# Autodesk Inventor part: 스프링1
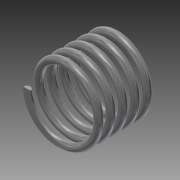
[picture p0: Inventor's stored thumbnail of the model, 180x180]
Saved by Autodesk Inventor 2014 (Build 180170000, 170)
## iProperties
Created: 2016-10
Part Number: 스프링1
Material: 강철, 탄소
Document SubType Name: Modeling
Designer: 703-16
Density: 7.87 g/cm^3
Appearance: 반연마
Mass: 6.8717 g
Surface Area: 17.7337 cm^2
Volume: 0.873151 cm^3
Author: 703-16
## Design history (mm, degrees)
sketch "스케치1"
  geometry: L1 (0, 0)-(-9, 0); L2 (-9, 0)-(-9, 16.67); L3 (-9, 16.67)-(0, 16.67); L4 (0, 16.67)-(0, 0); C1 r 1 at (-9, 0)
  constraints: 8 end point, 2 parallel, 1 centre point, 1 coincident, 1 horizontal, 1 perpendicular
  dimensions: "d0" = 16.66987 distance of L3.end L1.start (derived); "d1" = 2 diameter of C1; "d2" = 18 diameter of L2 L4
feature "코일1" sketch "스케치1" pitch "d3" = 10; turns "d5" = 5; dims "d4" = 16.66987 (= d0), "d6" = 0, angle "d7" = 90 deg, angle "d8" = 90 deg, "d9" = 0, "d10" = 0
node "작업 평면1"
sketch "스케치2"
  geometry: L1 (0, 0)-(-2, 0) reference; 1 further point
  constraints: 1 horizontal alignment
extrude "돌출1" cut sketch "스케치2" distance "d11" = 10; taper "d12" = 0 deg
sketch "스케치3"
  geometry: L1 (8, 0)-(10, 0) reference; 1 further point
  constraints: 1 horizontal alignment
extrude "돌출2" cut sketch "스케치3" distance "d13" = 10; taper "d14" = 0 deg
node "솔리드1"
node "절단 모서리 투영1"
node "절단 모서리 투영2"
